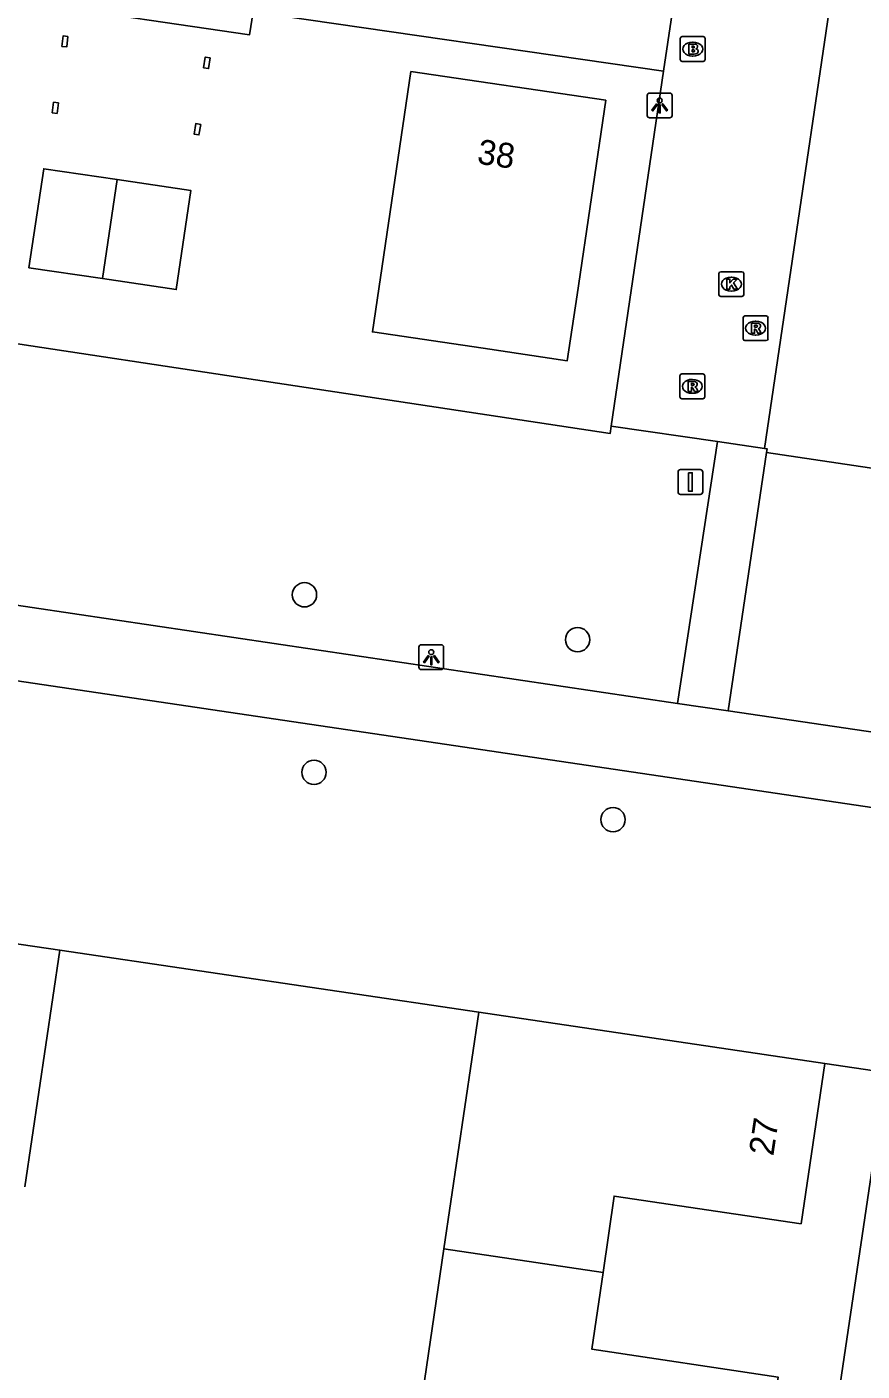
# Model space of a CAD drawing. Extents: x 164150 to 165261, y 382513 to 383432.
# Drawn here: x 164514.2 to 164547.8, y 382999.8 to 383053.9 of the extents above; entities that cross this region are included whole.
import ezdxf

# ---------------------------------------------------------------- set-up
doc = ezdxf.new("R2010")
doc.units = 0
for name, color, linetype in [('IMGEO_Boom', 7, 'Continuous'), ('IMGEO_Brandkraan', 7, 'Continuous'), ('IMGEO_Fietspad_gesloten', 7, 'Continuous'), ('IMGEO_Groenvoorziening', 7, 'Continuous'), ('IMGEO_Hek', 7, 'Continuous'), ('IMGEO_Kolk', 7, 'Continuous'), ('IMGEO_Lichtpunt', 7, 'Continuous'), ('IMGEO_Pand', 7, 'Continuous'), ('IMGEO_Pand_nummerreeks', 7, 'Continuous'), ('IMGEO_Rijbaan_lokaal_open', 7, 'Continuous'), ('IMGEO_Rioolput', 7, 'Continuous'), ('IMGEO_Verkeersbordpaal', 7, 'Continuous'), ('IMGEO_Voetpad_open', 7, 'Continuous')]:
    doc.layers.add(name, color=color, linetype=linetype)

msp = doc.modelspace()

# ---------------------------------------------------------------- linework, layer by layer
at = {"layer": 'IMGEO_Boom'}
for centre in [(164525.371, 383031.025), (164536.363, 383029.217), (164525.755, 383023.878), (164537.789, 383021.974)]:
    msp.add_circle(centre, 0.489, dxfattribs=at)
at = {"layer": 'IMGEO_Brandkraan'}
for p, q in [((164540.496, 383052.566), (164540.496, 383053.418)), ((164540.571, 383053.492), (164541.423, 383053.492)), ((164541.497, 383053.418), (164541.497, 383052.566)), ((164540.984, 383053.272), (164541.009, 383053.272)), ((164541.423, 383052.492), (164540.571, 383052.492)), ((164541.007, 383052.712), (164540.982, 383052.712))]:
    msp.add_line(p, q, dxfattribs=at)
for points in [[(164540.496, 383052.566), (164540.496, 383053.418)], [(164540.571, 383053.492), (164541.423, 383053.492)], [(164541.497, 383053.418), (164541.497, 383052.566)], [(164540.844, 383053.192), (164540.844, 383052.792), (164541.057, 383052.792)], [(164541.075, 383053.192), (164540.844, 383053.192)], [(164541.023, 383053.111), (164540.969, 383053.111), (164540.969, 383053.035)], [(164540.969, 383053.035), (164541.022, 383053.035)], [(164541.031, 383052.959), (164540.969, 383052.959), (164540.969, 383052.878)], [(164540.969, 383052.878), (164541.031, 383052.878)], [(164541.423, 383052.492), (164540.571, 383052.492)]]:
    msp.add_lwpolyline(points, dxfattribs=at)
for centre, radius, start, end in [((164540.573, 383053.416), 0.0765, 91.552, 178.448), ((164540.573, 383053.416), 0.0765, 91.552, 178.448), ((164541.421, 383053.416), 0.0765, 1.552, 88.448), ((164541.421, 383053.416), 0.0765, 1.552, 88.448), ((164541.024, 383053.073), 0.0379, 267.8285, 90.9355), ((164541.032, 383052.918), 0.0404, 269.8759, 90.5077), ((164541.079, 383053.047), 0.145, 59.4692, 91.5367), ((164541.104, 383053.094), 0.0922, 285.5137, 58.1501), ((164541.109, 383052.902), 0.105, 301.3115, 78.989), ((164540.573, 383052.568), 0.0765, 181.552, 268.448), ((164540.573, 383052.568), 0.0765, 181.552, 268.448), ((164541.063, 383053.043), 0.251, 268.6676, 293.5347), ((164541.421, 383052.568), 0.0765, 271.552, 358.448), ((164541.421, 383052.568), 0.0765, 271.552, 358.448)]:
    msp.add_arc(centre, radius, start, end, dxfattribs=at)
for centre, major_axis, ratio, start_param, end_param in [((164540.983, 383052.992), (-0.387, 0.002), 0.722429, 4.712389, 7.853982), ((164541.008, 383052.992), (-0.39, 0.002), 0.717154, 1.570796, 4.712389)]:
    msp.add_ellipse(centre, major_axis=major_axis, ratio=ratio, start_param=start_param, end_param=end_param, dxfattribs=at)
at = {"layer": 'IMGEO_Fietspad_gesloten'}
for points in [[(164541.991, 383037.193), (164540.385, 383026.655)], [(164542.422, 383026.352), (164543.97, 383036.746)], [(164543.882, 383036.919), (164543.993, 383036.903), (164543.97, 383036.746)], [(164540.385, 383026.655), (164491.665, 383033.898)], [(164557.267, 383021.125), (164497.229, 383030.019)], [(164542.422, 383026.352), (164540.385, 383026.655)], [(164599.963, 383017.871), (164542.422, 383026.352)]]:
    msp.add_lwpolyline(points, dxfattribs=at)
at = {"layer": 'IMGEO_Groenvoorziening'}
for points in [[(164498.474, 383043.442), (164537.669, 383037.513), (164537.713, 383037.811)], [(164543.97, 383036.746), (164597.503, 383028.776), (164597.531, 383028.965)], [(164532.389, 383014.218), (164515.519, 383016.715)], [(164548.758, 383011.551), (164548.794, 383011.791), (164548.68, 383011.808), (164546.311, 383012.162)]]:
    msp.add_lwpolyline(points, dxfattribs=at)
at = {"layer": 'IMGEO_Hek'}
for points in [[(164537.713, 383037.811), (164537.669, 383037.513), (164498.474, 383043.442)], [(164597.531, 383028.965), (164597.503, 383028.776), (164543.97, 383036.746)]]:
    msp.add_lwpolyline(points, dxfattribs=at)
at = {"layer": 'IMGEO_Kolk'}
for p, q in [((164542.053, 383043.104), (164542.053, 383043.956)), ((164542.128, 383044.03), (164542.98, 383044.03)), ((164542.541, 383043.81), (164542.566, 383043.81)), ((164543.054, 383043.956), (164543.054, 383043.104)), ((164542.564, 383043.25), (164542.539, 383043.25)), ((164542.98, 383043.03), (164542.128, 383043.03))]:
    msp.add_line(p, q, dxfattribs=at)
for points in [[(164542.053, 383043.104), (164542.053, 383043.956)], [(164542.128, 383044.03), (164542.98, 383044.03)], [(164542.374, 383043.73), (164542.497, 383043.73), (164542.497, 383043.579), (164542.627, 383043.73), (164542.791, 383043.73), (164542.645, 383043.579), (164542.798, 383043.33), (164542.646, 383043.33), (164542.561, 383043.494), (164542.497, 383043.427), (164542.497, 383043.33), (164542.374, 383043.33), (164542.374, 383043.73)], [(164543.054, 383043.956), (164543.054, 383043.104)], [(164542.98, 383043.03), (164542.128, 383043.03)]]:
    msp.add_lwpolyline(points, dxfattribs=at)
for centre, start, end in [((164542.13, 383043.954), 91.552, 178.448), ((164542.13, 383043.954), 91.552, 178.448), ((164542.978, 383043.954), 1.552, 88.448), ((164542.978, 383043.954), 1.552, 88.448), ((164542.13, 383043.106), 181.552, 268.448), ((164542.13, 383043.106), 181.552, 268.448), ((164542.978, 383043.106), 271.552, 358.448), ((164542.978, 383043.106), 271.552, 358.448)]:
    msp.add_arc(centre, 0.0765, start, end, dxfattribs=at)
for centre, major_axis, ratio, start_param, end_param in [((164542.54, 383043.53), (-0.387, 0.002), 0.722429, 4.712389, 7.853982), ((164542.565, 383043.53), (-0.39, 0.002), 0.717154, 1.570796, 4.712389)]:
    msp.add_ellipse(centre, major_axis=major_axis, ratio=ratio, start_param=start_param, end_param=end_param, dxfattribs=at)
at = {"layer": 'IMGEO_Lichtpunt'}
for p, q in [((164540.07, 383051.221), (164539.262, 383051.221)), ((164540.07, 383051.221), (164539.262, 383051.221)), ((164539.168, 383051.126), (164539.168, 383050.319)), ((164539.168, 383051.126), (164539.168, 383050.319)), ((164540.164, 383050.319), (164540.164, 383051.126)), ((164540.164, 383050.319), (164540.164, 383051.126)), ((164539.262, 383050.225), (164540.07, 383050.225)), ((164539.262, 383050.225), (164540.07, 383050.225)), ((164529.975, 383028.917), (164529.975, 383028.11)), ((164529.975, 383028.917), (164529.975, 383028.11)), ((164530.877, 383029.012), (164530.069, 383029.012)), ((164530.877, 383029.012), (164530.069, 383029.012)), ((164530.971, 383028.11), (164530.971, 383028.917)), ((164530.971, 383028.11), (164530.971, 383028.917)), ((164530.069, 383028.016), (164530.877, 383028.016)), ((164530.069, 383028.016), (164530.877, 383028.016))]:
    msp.add_line(p, q, dxfattribs=at)
for points in [[(164539.542, 383050.79), (164539.581, 383050.762), (164539.393, 383050.5), (164539.355, 383050.527), (164539.542, 383050.79)], [(164539.644, 383050.742), (164539.691, 383050.742), (164539.691, 383050.42), (164539.644, 383050.42), (164539.644, 383050.742)], [(164539.754, 383050.762), (164539.792, 383050.789), (164539.979, 383050.527), (164539.94, 383050.499), (164539.754, 383050.762)], [(164530.349, 383028.581), (164530.388, 383028.553), (164530.2, 383028.291), (164530.162, 383028.318), (164530.349, 383028.581)], [(164530.451, 383028.533), (164530.498, 383028.533), (164530.498, 383028.211), (164530.451, 383028.211), (164530.451, 383028.533)], [(164530.561, 383028.553), (164530.599, 383028.58), (164530.786, 383028.318), (164530.747, 383028.29), (164530.561, 383028.553)]]:
    msp.add_lwpolyline(points, dxfattribs=at)
for centre in [(164539.667, 383050.924), (164530.474, 383028.715)]:
    msp.add_circle(centre, 0.0994, dxfattribs=at)
for centre, start, end in [((164539.262, 383051.126), 90, 180), ((164539.262, 383051.126), 90, 180), ((164540.07, 383051.126), 0, 90), ((164540.07, 383051.126), 0, 90), ((164539.262, 383050.319), 180, 270), ((164539.262, 383050.319), 180, 270), ((164540.07, 383050.319), 270, 0), ((164540.07, 383050.319), 270, 360), ((164530.069, 383028.917), 90, 180), ((164530.069, 383028.917), 90, 180), ((164530.877, 383028.917), 0, 90), ((164530.877, 383028.917), 0, 90), ((164530.069, 383028.11), 180, 270), ((164530.069, 383028.11), 180, 270), ((164530.877, 383028.11), 270, 0), ((164530.877, 383028.11), 270, 360)]:
    msp.add_arc(centre, 0.0946, start, end, dxfattribs=at)
at = {"layer": 'IMGEO_Pand'}
for points in [[(164515.85, 383053.5), (164515.803, 383053.078), (164515.607, 383053.1), (164515.655, 383053.522), (164515.85, 383053.5)], [(164521.573, 383052.637), (164521.511, 383052.209), (164521.309, 383052.239), (164521.379, 383052.671), (164521.573, 383052.637)], [(164529.655, 383052.09), (164537.498, 383050.933), (164536.342, 383043.104), (164535.95, 383040.448), (164532.559, 383040.948), (164528.108, 383041.605), (164529.655, 383052.09)], [(164515.471, 383050.822), (164515.413, 383050.403), (164515.216, 383050.43), (164515.274, 383050.85), (164515.471, 383050.822)], [(164521.196, 383049.958), (164521.125, 383049.534), (164520.926, 383049.567), (164520.997, 383049.991), (164521.196, 383049.958)], [(164517.244, 383043.751), (164514.282, 383044.191), (164514.874, 383048.176), (164517.836, 383047.736)], [(164517.836, 383047.736), (164520.799, 383047.295), (164520.207, 383043.311), (164517.244, 383043.751)], [(164517.836, 383047.736), (164517.244, 383043.751)], [(164515.519, 383016.715), (164501.59, 383018.76)], [(164515.519, 383016.715), (164514.115, 383007.187)], [(164530.985, 383004.694), (164532.389, 383014.218)], [(164546.311, 383012.162), (164532.389, 383014.218)], [(164546.311, 383012.162), (164545.357, 383005.706), (164537.832, 383006.82), (164537.389, 383003.75)], [(164537.389, 383003.75), (164536.941, 383000.651), (164544.44, 382999.529), (164543.49, 382993.099), (164529.581, 382995.169), (164530.985, 383004.694)], [(164537.389, 383003.75), (164530.985, 383004.694)]]:
    msp.add_lwpolyline(points, dxfattribs=at)
at = {"layer": 'IMGEO_Rijbaan_lokaal_open'}
for points in [[(164547.597, 383062.105), (164543.882, 383036.919)], [(164539.82, 383052.102), (164523.309, 383054.494), (164523.162, 383053.567), (164514.538, 383054.823), (164515.325, 383060.467), (164524.006, 383059.166), (164523.899, 383058.249), (164540.378, 383055.886)], [(164539.82, 383052.102), (164540.378, 383055.886)], [(164537.713, 383037.811), (164539.82, 383052.102)], [(164537.713, 383037.811), (164541.991, 383037.193)], [(164543.882, 383036.919), (164541.991, 383037.193)]]:
    msp.add_lwpolyline(points, dxfattribs=at)
at = {"layer": 'IMGEO_Rioolput'}
for p, q in [((164543.026, 383041.329), (164543.026, 383042.181)), ((164543.101, 383042.255), (164543.953, 383042.255)), ((164543.514, 383042.035), (164543.539, 383042.035)), ((164544.027, 383042.181), (164544.027, 383041.329)), ((164543.537, 383041.475), (164543.512, 383041.475)), ((164543.953, 383041.255), (164543.101, 383041.255)), ((164540.556, 383039.914), (164541.408, 383039.914)), ((164540.481, 383038.988), (164540.481, 383039.84)), ((164540.969, 383039.694), (164540.994, 383039.694)), ((164541.482, 383039.84), (164541.482, 383038.988)), ((164541.408, 383038.914), (164540.556, 383038.914)), ((164540.992, 383039.134), (164540.967, 383039.134))]:
    msp.add_line(p, q, dxfattribs=at)
for points in [[(164543.026, 383041.329), (164543.026, 383042.181)], [(164543.101, 383042.255), (164543.953, 383042.255)], [(164544.027, 383042.181), (164544.027, 383041.329)], [(164543.615, 383041.953), (164543.363, 383041.955), (164543.363, 383041.555)], [(164543.363, 383041.555), (164543.487, 383041.555), (164543.487, 383041.717), (164543.498, 383041.717)], [(164543.541, 383041.874), (164543.487, 383041.874), (164543.487, 383041.793)], [(164543.487, 383041.793), (164543.539, 383041.793)], [(164543.545, 383041.688), (164543.616, 383041.555), (164543.756, 383041.555), (164543.691, 383041.681)], [(164543.953, 383041.255), (164543.101, 383041.255)], [(164540.556, 383039.914), (164541.408, 383039.914)], [(164540.481, 383038.988), (164540.481, 383039.84)], [(164541.07, 383039.612), (164540.818, 383039.614), (164540.818, 383039.214)], [(164540.818, 383039.214), (164540.942, 383039.214), (164540.942, 383039.376), (164540.953, 383039.376)], [(164540.996, 383039.533), (164540.942, 383039.533), (164540.942, 383039.452)], [(164540.942, 383039.452), (164540.994, 383039.452)], [(164541, 383039.347), (164541.071, 383039.214), (164541.211, 383039.214), (164541.146, 383039.34)], [(164541.482, 383039.84), (164541.482, 383038.988)], [(164541.408, 383038.914), (164540.556, 383038.914)]]:
    msp.add_lwpolyline(points, dxfattribs=at)
for centre, radius, start, end in [((164543.103, 383042.179), 0.0765, 91.552, 178.448), ((164543.103, 383042.179), 0.0765, 91.552, 178.448), ((164543.951, 383042.179), 0.0765, 1.552, 88.448), ((164543.951, 383042.179), 0.0765, 1.552, 88.448), ((164543.497, 383041.664), 0.0533, 26.0293, 88.6989), ((164543.523, 383041.982), 0.19, 274.7715, 282.9687), ((164543.547, 383041.778), 0.0964, 77.0061, 93.1865), ((164543.561, 383041.835), 0.0378, 276.6634, 79.6772), ((164543.614, 383041.843), 0.109, 350.3612, 89.416), ((164543.612, 383041.843), 0.112, 277.5842, 350.9817), ((164543.596, 383041.628), 0.108, 29.5134, 73.7905), ((164543.103, 383041.331), 0.0765, 181.552, 268.448), ((164543.103, 383041.331), 0.0765, 181.552, 268.448), ((164543.951, 383041.331), 0.0765, 271.552, 358.448), ((164543.951, 383041.331), 0.0765, 271.552, 358.448), ((164540.558, 383039.838), 0.0765, 91.552, 178.448), ((164540.558, 383039.838), 0.0765, 91.552, 178.448), ((164541.406, 383039.838), 0.0765, 1.552, 88.448), ((164541.406, 383039.838), 0.0765, 1.552, 88.448), ((164540.952, 383039.323), 0.0533, 26.0293, 88.6989), ((164540.978, 383039.641), 0.19, 274.7715, 282.9687), ((164541.002, 383039.437), 0.0964, 77.0061, 93.1865), ((164541.016, 383039.494), 0.0378, 276.6634, 79.6772), ((164541.069, 383039.502), 0.109, 350.3612, 89.416), ((164541.067, 383039.502), 0.112, 277.5842, 350.9817), ((164541.051, 383039.287), 0.108, 29.5134, 73.7905), ((164540.558, 383038.99), 0.0765, 181.552, 268.448), ((164540.558, 383038.99), 0.0765, 181.552, 268.448), ((164541.406, 383038.99), 0.0765, 271.552, 358.448), ((164541.406, 383038.99), 0.0765, 271.552, 358.448)]:
    msp.add_arc(centre, radius, start, end, dxfattribs=at)
for centre, major_axis, ratio, start_param, end_param in [((164543.513, 383041.755), (-0.387, 0.002), 0.722429, 4.712389, 7.853982), ((164543.538, 383041.755), (-0.39, 0.002), 0.717154, 1.570796, 4.712389), ((164540.968, 383039.414), (-0.387, 0.002), 0.722429, 4.712389, 7.853982), ((164540.993, 383039.414), (-0.39, 0.002), 0.717154, 1.570796, 4.712389)]:
    msp.add_ellipse(centre, major_axis=major_axis, ratio=ratio, start_param=start_param, end_param=end_param, dxfattribs=at)
at = {"layer": 'IMGEO_Verkeersbordpaal'}
for p, q in [((164540.508, 383036.065), (164541.298, 383036.065)), ((164541.298, 383036.065), (164540.508, 383036.065)), ((164540.408, 383035.165), (164540.408, 383035.965)), ((164540.408, 383035.965), (164540.408, 383035.165)), ((164541.398, 383035.965), (164541.398, 383035.165)), ((164541.398, 383035.165), (164541.398, 383035.965)), ((164541.298, 383035.065), (164540.508, 383035.065)), ((164540.508, 383035.065), (164541.298, 383035.065))]:
    msp.add_line(p, q, dxfattribs=at)
msp.add_lwpolyline([(164540.828, 383035.94), (164540.978, 383035.94), (164540.978, 383035.19), (164540.828, 383035.19), (164540.828, 383035.94)], dxfattribs=at)
for centre, start, end in [((164540.508, 383035.965), 90, 180), ((164540.508, 383035.965), 90, 180), ((164541.298, 383035.965), 0, 90), ((164541.298, 383035.965), 360, 90), ((164540.508, 383035.165), 180, 270), ((164540.508, 383035.165), 180, 270), ((164541.298, 383035.165), 270, 0), ((164541.298, 383035.165), 270, 0)]:
    msp.add_arc(centre, 0.1, start, end, dxfattribs=at)
at = {"layer": 'IMGEO_Voetpad_open'}
msp.add_lwpolyline([(164496.276, 383000.022), (164545.95, 382992.647), (164548.758, 383011.551)], dxfattribs=at)

# ---------------------------------------------------------------- texts
at = {"layer": 'IMGEO_Pand_nummerreeks'}
for s, rotation, p in [('38', 351.6062, (164532.286, 383048.387)), ('27', 81.5949, (164544.24, 383008.408))]:
    msp.add_text(s, height=1, rotation=rotation, dxfattribs=at).set_placement(p)

doc.saveas('drawing.dxf')
